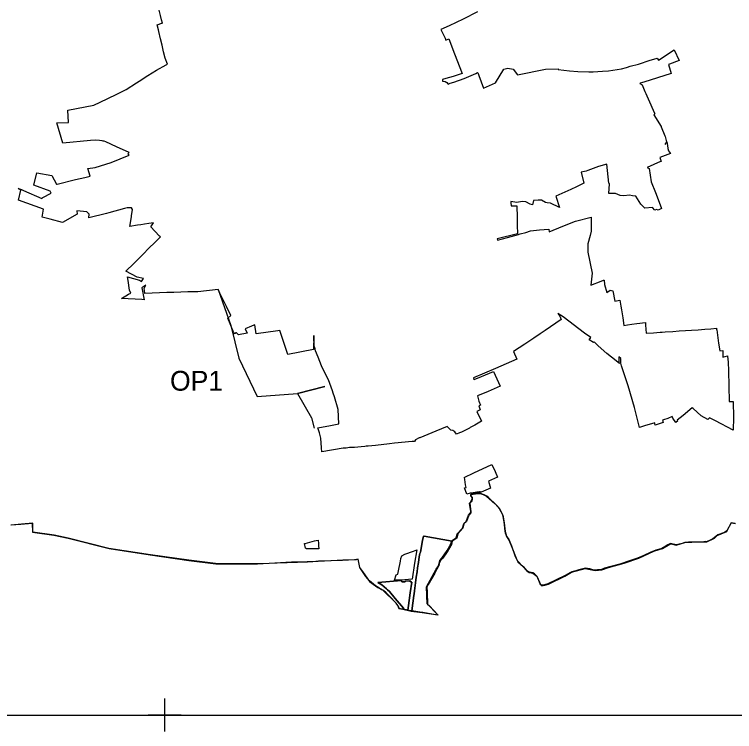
# Model space of a CAD drawing. Extents: x -478490 to -472450, y -1118050 to -1109550.
# Drawn here: x -477155 to -474975, y -1118050 to -1115880 of the extents above; entities that cross this region are included whole.
import ezdxf

# ---------------------------------------------------------------- set-up
doc = ezdxf.new("R2010")
doc.units = 0
for name, color, linetype in [('hranice kú', 7, 'Continuous'), ('Implicitní', 7, 'Continuous'), ('ObPÚ', 7, 'Continuous')]:
    doc.layers.add(name, color=color, linetype=linetype)

msp = doc.modelspace()

# ---------------------------------------------------------------- linework, layer by layer
at = {"layer": 'hranice kú'}
for p, q in [((-475773.3, -1117332.4), (-475752, -1117329.2)), ((-475772.9, -1117337.3), (-475773.3, -1117332.4)), ((-475773.1, -1117354.3), (-475768.7, -1117344)), ((-475770, -1117340.3), (-475772.9, -1117337.3)), ((-475768.7, -1117344), (-475770, -1117340.3)), ((-475752, -1117329.2), (-475745.4, -1117329.5)), ((-475745.4, -1117329.5), (-475736, -1117333)), ((-475736, -1117333), (-475725.4, -1117338.1)), ((-475725.4, -1117338.1), (-475700.6, -1117360.1)), ((-475777.5, -1117358.9), (-475773.1, -1117354.3)), ((-475773.7, -1117384.2), (-475777.5, -1117358.9)), ((-475700.6, -1117360.1), (-475690.7, -1117370.6)), ((-475780.7, -1117395.1), (-475774.1, -1117388)), ((-475774.1, -1117388), (-475773.7, -1117384.2)), ((-475690.7, -1117370.6), (-475685.4, -1117378)), ((-475685.4, -1117378), (-475676.7, -1117395.1)), ((-475787.5, -1117414.7), (-475780.7, -1117395.1)), ((-475676.7, -1117395.1), (-475671.9, -1117417.9)), ((-477165.8, -1117424.6), (-477134.7, -1117422.1)), ((-477134.7, -1117422.1), (-477100.4, -1117419)), ((-477100.4, -1117419), (-477099.3, -1117446.8)), ((-475798.5, -1117434.6), (-475794.6, -1117421.1)), ((-475794.6, -1117421.1), (-475787.5, -1117414.7)), ((-475671.9, -1117417.9), (-475669.7, -1117444.5)), ((-474998.9, -1117444.1), (-474985.7, -1117418)), ((-474985.7, -1117418), (-474972, -1117420.4)), ((-477099.3, -1117446.8), (-477035.2, -1117455.8)), ((-475817.6, -1117464.1), (-475814.3, -1117451.4)), ((-475814.3, -1117451.4), (-475798.5, -1117434.6)), ((-475669.7, -1117444.5), (-475665.3, -1117458.5)), ((-475027.8, -1117457.1), (-474998.9, -1117444.1)), ((-477035.2, -1117455.8), (-476991.4, -1117464.9)), ((-476991.4, -1117464.9), (-476867.7, -1117495.9)), ((-475833, -1117480.7), (-475831.5, -1117473.2)), ((-475831.5, -1117473.2), (-475817.6, -1117464.1)), ((-475665.3, -1117458.5), (-475658.2, -1117469.2)), ((-475658.2, -1117469.2), (-475650.2, -1117488)), ((-475059, -1117476.2), (-475035.7, -1117464.8)), ((-475035.7, -1117464.8), (-475027.8, -1117457.1)), ((-476867.7, -1117495.9), (-476743.2, -1117515.4)), ((-475844.9, -1117501.8), (-475835.7, -1117486.1)), ((-475835.7, -1117486.1), (-475833, -1117480.7)), ((-475650.2, -1117488), (-475638.7, -1117519.8)), ((-475219.6, -1117504.2), (-475193.7, -1117496.3)), ((-475193.7, -1117496.3), (-475171.4, -1117482.5)), ((-475171.4, -1117482.5), (-475166.6, -1117481.7)), ((-475166.6, -1117481.7), (-475151.7, -1117486)), ((-475151.7, -1117486), (-475125.2, -1117477.7)), ((-475125.2, -1117477.7), (-475104.3, -1117477.2)), ((-475104.3, -1117477.2), (-475059, -1117476.2)), ((-476743.2, -1117515.4), (-476626.6, -1117532.5)), ((-475860.6, -1117525.1), (-475844.9, -1117501.8)), ((-475264.7, -1117524.8), (-475219.6, -1117504.2)), ((-476626.6, -1117532.5), (-476544.9, -1117542)), ((-476419.1, -1117542), (-476383.4, -1117540.4)), ((-476383.4, -1117540.4), (-476335, -1117538.6)), ((-476161.9, -1117531.2), (-476125.1, -1117529.7)), ((-476125.1, -1117529.7), (-476118.9, -1117528.8)), ((-476118.9, -1117528.8), (-476114.9, -1117528.2)), ((-476114.9, -1117528.2), (-476109.7, -1117553.1)), ((-475871.5, -1117548.3), (-475867, -1117532.2)), ((-475867, -1117532.2), (-475860.6, -1117525.1)), ((-475638.7, -1117519.8), (-475631.3, -1117536.1)), ((-475631.3, -1117536.1), (-475615.2, -1117550.7)), ((-475357.1, -1117553.3), (-475309.3, -1117540.8)), ((-475309.3, -1117540.8), (-475264.7, -1117524.8)), ((-476544.9, -1117542), (-476419.1, -1117542)), ((-476109.7, -1117553.1), (-476101, -1117565.5)), ((-475884.7, -1117569.8), (-475878.1, -1117558.5)), ((-475878.1, -1117558.5), (-475871.5, -1117548.3)), ((-475615.2, -1117550.7), (-475604.2, -1117563.4)), ((-475468.7, -1117568), (-475426.9, -1117556.4)), ((-475426.9, -1117556.4), (-475397.4, -1117562.5)), ((-475397.4, -1117562.5), (-475376.6, -1117560.5)), ((-475376.6, -1117560.5), (-475357.1, -1117553.3)), ((-476101, -1117565.5), (-476080.1, -1117595.4)), ((-475907.7, -1117611.9), (-475884.7, -1117569.8)), ((-475604.2, -1117563.4), (-475596.5, -1117568.1)), ((-475596.5, -1117568.1), (-475585.2, -1117571.1)), ((-475585.2, -1117571.1), (-475573.8, -1117579.5)), ((-475573.8, -1117579.5), (-475565.7, -1117598.2)), ((-475538.1, -1117603.7), (-475489.2, -1117579.7)), ((-475489.2, -1117579.7), (-475468.7, -1117568)), ((-476080.1, -1117595.4), (-476057.9, -1117611.9)), ((-475565.7, -1117598.2), (-475562.9, -1117604.6)), ((-475562.9, -1117604.6), (-475558.3, -1117608.5)), ((-475549.6, -1117607.3), (-475538.1, -1117603.7)), ((-476057.9, -1117611.9), (-476054.4, -1117613.8)), ((-476054.4, -1117613.8), (-476051.1, -1117615.7)), ((-476051.1, -1117615.7), (-476048.5, -1117617)), ((-476048.5, -1117617), (-476046.4, -1117618.3)), ((-476046.4, -1117618.3), (-476043.5, -1117619.9)), ((-476043.5, -1117619.9), (-476040.8, -1117621.3)), ((-476040.8, -1117621.3), (-476035.4, -1117626.1)), ((-476035.4, -1117626.1), (-476004.1, -1117656)), ((-475905.2, -1117663.1), (-475907.7, -1117611.9)), ((-475558.3, -1117608.5), (-475549.6, -1117607.3)), ((-476004.1, -1117656), (-475996, -1117665.9)), ((-475996, -1117665.9), (-475991.2, -1117677.6)), ((-475872.8, -1117696.5), (-475905.2, -1117663.1)), ((-475991.2, -1117677.6), (-475978.7, -1117679.6)), ((-475978.7, -1117679.6), (-475953.9, -1117685.4)), ((-475953.9, -1117685.4), (-475920.8, -1117690)), ((-475920.8, -1117690), (-475872.8, -1117696.5))]:
    msp.add_line(p, q, dxfattribs=at)
msp.add_lwpolyline([(-476335, -1117538.6), (-476331.3, -1117538.5), (-476328.9, -1117538.5), (-476309.5, -1117537.6), (-476304, -1117537.5), (-476297.9, -1117537.3), (-476282.7, -1117536.7), (-476267.7, -1117535.9), (-476235.2, -1117534.5), (-476196.6, -1117532.7), (-476161.9, -1117531.2)], dxfattribs=at)
at = {"layer": 'Implicitní'}
for p, q in [((-476700.1, -1117950.1), (-476700.1, -1118050.1)), ((-476650.1, -1118000.1), (-476750.1, -1118000.1))]:
    msp.add_line(p, q, dxfattribs=at)
msp.add_lwpolyline([(-478440.1, -1118000.1), (-472500.1, -1118000.1), (-472500.1, -1109600.1), (-478440.1, -1109600.1)], close=True, dxfattribs=at)
msp.add_lwpolyline([(-476537.9, -1116712.5), (-476499.6, -1116820.8), (-476475.1, -1116919.5), (-476420.2, -1117035.8), (-476297.4, -1117027.1), (-476215, -1117005.8), (-476297.4, -1117027.1), (-476255.6, -1117100.3), (-476255.6, -1117100.3), (-476247.5, -1117131.7)], dxfattribs=at)
at = {"layer": 'ObPÚ'}
for p, q in [((-475744.6, -1117324.7), (-475747, -1117324)), ((-475742.5, -1117325.3), (-475744.6, -1117324.7))]:
    msp.add_line(p, q, dxfattribs=at)
for points in [[(-476716.8, -1116549.4), (-476742.1, -1116522.2), (-476733.5, -1116510), (-476747.3, -1116512.3), (-476761, -1116514.4), (-476772.2, -1116516.4), (-476782.1, -1116517.8), (-476805.1, -1116521.1), (-476800.4, -1116492.3), (-476799.8, -1116488.9), (-476796.8, -1116469.7), (-476799.8, -1116465.1), (-476813.2, -1116464.9), (-476821.5, -1116467.2), (-476869, -1116480.1), (-476875.9, -1116482), (-476929.6, -1116495.7), (-476928.6, -1116484.7), (-476935.1, -1116477.1), (-476965.2, -1116473.8), (-476964.1, -1116483.8), (-477009.1, -1116509.9), (-477046.3, -1116499.5), (-477070.7, -1116493.1), (-477066, -1116469.4), (-477142.6, -1116441.9), (-477135.3, -1116411.7), (-477143.2, -1116406.4), (-477133.2, -1116409.5), (-477127, -1116412.2), (-477072, -1116436.3), (-477068.2, -1116434.2), (-477043, -1116420.5), (-477046.2, -1116414.4), (-477096.2, -1116396.9), (-477087, -1116359.4), (-477041.6, -1116367.7), (-477027.1, -1116393.6), (-477024.7, -1116393), (-476969.7, -1116379.8), (-476941.5, -1116373.1), (-476924.9, -1116369.2), (-476932, -1116346), (-476910.3, -1116342.8), (-476862, -1116327.9), (-476806.8, -1116306.1), (-476811.6, -1116302), (-476807.6, -1116298), (-476845.7, -1116280.1), (-476878, -1116265), (-476883.2, -1116263.6), (-476885.7, -1116263.1), (-476889.1, -1116262.6), (-476896.8, -1116261.7), (-476908.9, -1116260.2), (-476924.1, -1116261.6), (-477007.9, -1116269), (-477025.9, -1116207.4), (-476990.5, -1116207), (-476992.4, -1116169.7), (-476913.9, -1116154.4), (-476895, -1116145), (-476846.1, -1116121.6), (-476816.5, -1116106.9), (-476785, -1116086.7), (-476776.6, -1116081.3), (-476750.7, -1116064.8), (-476724.3, -1116048.2), (-476695, -1116031.9), (-476691.4, -1116029.9), (-476697.9, -1116011.9), (-476703.4, -1115992.7), (-476707.7, -1115973.2), (-476712.7, -1115953.4), (-476717.9, -1115931.2), (-476718.9, -1115926.7), (-476722.5, -1115911.7), (-476708, -1115906.3), (-476706.6, -1115905.8), (-476709.3, -1115896.3), (-476712.4, -1115883.4), (-476716.3, -1115867)], [(-475753.2, -1115871.8), (-475796.4, -1115894.5), (-475838.6, -1115914.6), (-475863.6, -1115925.3), (-475850.8, -1115952.1), (-475848.8, -1115957.6), (-475839.8, -1115954), (-475822.7, -1115998.9), (-475799.8, -1116058.4), (-475826.7, -1116067.4), (-475849.1, -1116073.9), (-475859, -1116076.8), (-475858.5, -1116081.8), (-475850.5, -1116082.4), (-475846, -1116085.5), (-475841.5, -1116090.5), (-475835.8, -1116087.6), (-475824.7, -1116084.4), (-475793.6, -1116073.2), (-475757.8, -1116058.6), (-475752.6, -1116055.2), (-475751.9, -1116056.2), (-475751.3, -1116058.9), (-475749.1, -1116064.3), (-475735.2, -1116103), (-475699, -1116087), (-475673.7, -1116045.3), (-475661.5, -1116042.2), (-475645.4, -1116045.7), (-475632.5, -1116062.8), (-475547.6, -1116045), (-475509.3, -1116044.8), (-475509.4, -1116046.9), (-475475.1, -1116050.7), (-475449.8, -1116052.2), (-475416.4, -1116053.9), (-475403.4, -1116053.3), (-475374.7, -1116051.3), (-475356.5, -1116050.4), (-475317.7, -1116043.9), (-475302.2, -1116039.9), (-475298.9, -1116039.2), (-475291.5, -1116036.7), (-475266.1, -1116030), (-475230.2, -1116017.8), (-475212.6, -1116013.1), (-475209, -1116012.4), (-475205, -1116017.9), (-475157.9, -1115986.7), (-475143.1, -1116018.7), (-475171.7, -1116030.3), (-475175.1, -1116031.6), (-475166.6, -1116058.8), (-475250, -1116085.1), (-475260.4, -1116087.5), (-475261.4, -1116089.2), (-475254.8, -1116092.9), (-475246.3, -1116113), (-475243.5, -1116119.3), (-475240.6, -1116126), (-475236.6, -1116135), (-475217.4, -1116178.1), (-475216.4, -1116180.6), (-475219.2, -1116183.5), (-475197.7, -1116219.3), (-475197.5, -1116220.1), (-475186.2, -1116246.7), (-475185.4, -1116248.9), (-475181.2, -1116265.4), (-475185.4, -1116273.3), (-475179.8, -1116265.2), (-475178.2, -1116276.8), (-475177.1, -1116285), (-475175.1, -1116292.7)], [(-475175.1, -1116292.7), (-475169.4, -1116300.7), (-475201.2, -1116312.9), (-475197.7, -1116324.4), (-475199.7, -1116325.2), (-475239.7, -1116342.5), (-475233.8, -1116345.8), (-475227.7, -1116385.9), (-475214.4, -1116418.3), (-475197.3, -1116464.1), (-475196.2, -1116466.6), (-475206.7, -1116472.6), (-475211.8, -1116470.3), (-475216.6, -1116472.3), (-475223.2, -1116464.3), (-475246.3, -1116465.9), (-475258.3, -1116454.1), (-475273.6, -1116430.2), (-475283.6, -1116428.6), (-475293.4, -1116427.1), (-475310, -1116428.3), (-475321.7, -1116428), (-475335.4, -1116421.9), (-475355.5, -1116421.9), (-475353.9, -1116392.4), (-475355.8, -1116390.7), (-475361.4, -1116332.7), (-475386.9, -1116339.9), (-475419.2, -1116352.4), (-475423.8, -1116353.6), (-475439, -1116357.5), (-475430.9, -1116390.6), (-475453.5, -1116401.6), (-475470.5, -1116409.5), (-475516.3, -1116429.6), (-475504.9, -1116463.8), (-475531.9, -1116451.3), (-475542.4, -1116449.8), (-475547.1, -1116448.7), (-475559.9, -1116441.8), (-475569.8, -1116442.1), (-475583.6, -1116442.6), (-475586.4, -1116455.5), (-475593.7, -1116453.8), (-475606.8, -1116446.9), (-475618.2, -1116446.2), (-475633.8, -1116448.7), (-475652, -1116445.7), (-475652.2, -1116449.6), (-475650.9, -1116458.7), (-475634, -1116458.7), (-475633.3, -1116494.1), (-475633, -1116516.4), (-475632.9, -1116517.5), (-475631.8, -1116543.6), (-475693.2, -1116558.8), (-475692.2, -1116562.7), (-475661.8, -1116554.6), (-475628.7, -1116545.5), (-475623.9, -1116544.2), (-475607, -1116540), (-475592.9, -1116535.1), (-475565.4, -1116531.9), (-475537.3, -1116529.1), (-475536.7, -1116537.2), (-475494.7, -1116520.7), (-475456.5, -1116505.8), (-475409.4, -1116493.6), (-475409.3, -1116535.9), (-475412.3, -1116549), (-475419.4, -1116573.5), (-475419, -1116599.7), (-475406.5, -1116662.9), (-475410.2, -1116698.6), (-475379.2, -1116686.8), (-475372.2, -1116684.3), (-475370, -1116683.5), (-475368.5, -1116696.7), (-475361.8, -1116721.1), (-475351.9, -1116714.1), (-475343.5, -1116716.4), (-475337.6, -1116747.5), (-475322.6, -1116744.6), (-475319.8, -1116762.9), (-475317.8, -1116774.1), (-475313.4, -1116797.9), (-475310.2, -1116821.1), (-475299.6, -1116819.4), (-475286, -1116817.2), (-475271, -1116814.7), (-475244.9, -1116812.1), (-475244.2, -1116820), (-475242.4, -1116844.2), (-475220.3, -1116843.3), (-475200.7, -1116841.8), (-475194.4, -1116841.2)], [(-475821.3, -1117143.2), (-475827.5, -1117139.1), (-475834.2, -1117137.6), (-475844.4, -1117127.1), (-475878.8, -1117141), (-475928, -1117160.8), (-475929.8, -1117161.5), (-475941.2, -1117167.3), (-475944, -1117172.5), (-475951.3, -1117172.4), (-476004.5, -1117177.3), (-476018.9, -1117179.2), (-476061.7, -1117184), (-476084.3, -1117186.2), (-476089.5, -1117186.6), (-476094, -1117187), (-476104.8, -1117188), (-476125.8, -1117190), (-476140.4, -1117190.8), (-476151, -1117191.9), (-476159.5, -1117192.8), (-476224.1, -1117203.1), (-476225.4, -1117191.1), (-476226.7, -1117162.3), (-476231.3, -1117146.2), (-476236.3, -1117130.9), (-476197.9, -1117123.9), (-476173.1, -1117118.5), (-476175.1, -1117075.5), (-476185.9, -1117036.7), (-476189.6, -1117026.3), (-476192, -1117018.9), (-476203.9, -1116985.9), (-476220.3, -1116954.1), (-476224.8, -1116942.7), (-476235.1, -1116917.1), (-476243.4, -1116897.3), (-476244.9, -1116886.6), (-476247.7, -1116887.1), (-476248.8, -1116851.6), (-476249, -1116893.6), (-476326.6, -1116908.5), (-476339.7, -1116869.9), (-476351, -1116836.6), (-476357.4, -1116837.7), (-476422.9, -1116845.9), (-476427.4, -1116819.4), (-476430.3, -1116820.4), (-476436.9, -1116823.5), (-476455.7, -1116831.7), (-476450.1, -1116844), (-476476, -1116849.4), (-476482.1, -1116843.1), (-476483.7, -1116843.8), (-476488.8, -1116845.9), (-476490.1, -1116842.9), (-476509, -1116798.8), (-476499.6, -1116790.5), (-476512.7, -1116763.7), (-476522.7, -1116743.4), (-476532.6, -1116723.3), (-476537.9, -1116712.5), (-476599.3, -1116718.8), (-476629.5, -1116719.4), (-476650.7, -1116720.2), (-476671.7, -1116720.8), (-476692.9, -1116721.6), (-476759.4, -1116724), (-476760.7, -1116714.9), (-476761.7, -1116709.6), (-476757.2, -1116699.1), (-476768.7, -1116707.4), (-476762, -1116743), (-476768.7, -1116742.8), (-476830.9, -1116739.2), (-476809.4, -1116726.4), (-476801.8, -1116722.8), (-476806.4, -1116714.5), (-476810.3, -1116684.8), (-476811.8, -1116673.6), (-476775.7, -1116683.8), (-476770.1, -1116687.8), (-476764, -1116678.9), (-476783.5, -1116674.4), (-476817.6, -1116656.8), (-476793.5, -1116634), (-476780, -1116620.5), (-476777, -1116617.7), (-476761.2, -1116601.3), (-476751.7, -1116591.3), (-476745.1, -1116584.2), (-476732.8, -1116572.5), (-476722.4, -1116563.2), (-476712.3, -1116553.3), (-476715.3, -1116551), (-476716.8, -1116549.4)], [(-475194.4, -1116841.2), (-475185.4, -1116840.5), (-475161.7, -1116839.1), (-475142.9, -1116837.6), (-475124, -1116836.4), (-475105, -1116835), (-475085.7, -1116834.1), (-475065.1, -1116832.4), (-475047.4, -1116830.9), (-475030, -1116829.5), (-475029.4, -1116833.9), (-475028.6, -1116833.9), (-475023.8, -1116874.9), (-475019.8, -1116897.4), (-475011, -1116896.8), (-475010.4, -1116909.6), (-475010.4, -1116916.5), (-474996.6, -1116913), (-474996.4, -1116914.1), (-474994.6, -1116931.6), (-474993.4, -1116958.1), (-474991.2, -1117050.8), (-474978.9, -1117051.1), (-474978.1, -1117099.4), (-474979.1, -1117137.4), (-475032.7, -1117109.2), (-475050.7, -1117100.4), (-475056.1, -1117105.6), (-475076, -1117094.2), (-475100.9, -1117072.7), (-475103.2, -1117070.5), (-475130.9, -1117093.6), (-475148.6, -1117107.7), (-475146.9, -1117109.8), (-475153.2, -1117114.5), (-475161.6, -1117101.4), (-475164.2, -1117097), (-475176.8, -1117102.4), (-475190.4, -1117106.6), (-475193, -1117107.4), (-475191.2, -1117114.5), (-475215, -1117122.7), (-475216.2, -1117118.1), (-475216.8, -1117115.6), (-475247.6, -1117125.1), (-475262.7, -1117129.7), (-475267.7, -1117109.4), (-475278.3, -1117069.6), (-475297.5, -1117003.4), (-475317.6, -1116942.9), (-475319.3, -1116935), (-475319.6, -1116920.8), (-475325.4, -1116915.5), (-475324.9, -1116932.2), (-475323.6, -1116936.3), (-475347.7, -1116917), (-475362, -1116905.8), (-475387.6, -1116882.8), (-475400.2, -1116870.4), (-475402.3, -1116872.8), (-475415.1, -1116864), (-475409.9, -1116857), (-475429, -1116844), (-475493.6, -1116794.9), (-475510, -1116785), (-475504.4, -1116792.7), (-475500.2, -1116802.9), (-475548.7, -1116836.1), (-475563.2, -1116845.9), (-475582.4, -1116859), (-475609.9, -1116877.6), (-475644, -1116900.2), (-475634.1, -1116923.5), (-475698.2, -1116950.9), (-475765.5, -1116979.2), (-475764.2, -1116985.3), (-475762.8, -1116984.7), (-475740.8, -1116975.6), (-475704.4, -1116959.9), (-475684.8, -1117005), (-475721.1, -1117020.7), (-475752.9, -1117034.2), (-475749.2, -1117050), (-475744.5, -1117062.5), (-475748.9, -1117064.2), (-475744.9, -1117076.6), (-475754.6, -1117081.6), (-475740.7, -1117110.4), (-475761.5, -1117122.4), (-475769.3, -1117126.9), (-475775.6, -1117130.1), (-475776.9, -1117131.4), (-475801.9, -1117143.8), (-475807.1, -1117146.1), (-475816.2, -1117150.3), (-475821.3, -1117143.2)], [(-475710, -1117241.8), (-475709.1, -1117243.6), (-475700.1, -1117263.1), (-475692.4, -1117280.1), (-475720.3, -1117292.4), (-475713.9, -1117313), (-475742.3, -1117325.9), (-475744.3, -1117325.4), (-475747.1, -1117325.2), (-475755.1, -1117325.3), (-475766.7, -1117327.6), (-475774.9, -1117328.9), (-475785.3, -1117331.9), (-475792, -1117312.6), (-475790.1, -1117312), (-475787.6, -1117311.1), (-475788.9, -1117303), (-475791.1, -1117287.2), (-475791.6, -1117285.8), (-475792.8, -1117282.4), (-475793.3, -1117280.9), (-475763.7, -1117266.8), (-475710, -1117241.8)], [(-475198.5, -1117496.9), (-475213.9, -1117501.5), (-475228.9, -1117507.4), (-475249.6, -1117517.1), (-475268.9, -1117525.3), (-475289.9, -1117532.2), (-475322.2, -1117543.7), (-475349.4, -1117550.5), (-475368.4, -1117555.9), (-475377.8, -1117559.3), (-475383.5, -1117560.7), (-475389.5, -1117560.4), (-475400.9, -1117561.8), (-475413.6, -1117557.9), (-475426.3, -1117555.6), (-475446.3, -1117560.1), (-475455.6, -1117563.4), (-475467.2, -1117566.3), (-475474.1, -1117569.3), (-475488, -1117577.9), (-475515.5, -1117590.5), (-475540.5, -1117602.8), (-475554.8, -1117606.9), (-475558.9, -1117606.6), (-475561.4, -1117605.6), (-475563.8, -1117603.3), (-475572.2, -1117580.4), (-475580.7, -1117572.9), (-475585.9, -1117569.9), (-475595.6, -1117567.1), (-475604.5, -1117562.3), (-475615.8, -1117550), (-475631.3, -1117534.8), (-475635.3, -1117526.5), (-475648.5, -1117493.4), (-475653.1, -1117480.5), (-475657.3, -1117471.2), (-475665.2, -1117457.3), (-475668.2, -1117449.8), (-475669.4, -1117443.4), (-475672.3, -1117415.6), (-475676.7, -1117394.5), (-475681.4, -1117384.9), (-475687.6, -1117373.9), (-475695.2, -1117364.7), (-475720.1, -1117341.3), (-475725.2, -1117337.8), (-475733.2, -1117333.4), (-475747.2, -1117328.6), (-475754.8, -1117328.7), (-475760.6, -1117329.4), (-475770.6, -1117331.7), (-475773.2, -1117331.8), (-475773.5, -1117335), (-475772.5, -1117337.4), (-475769.1, -1117340.7), (-475769.1, -1117342.3), (-475769.2, -1117346.8), (-475770, -1117352.1), (-475772.1, -1117354.5), (-475776.3, -1117358.9), (-475773, -1117385.1), (-475773.4, -1117388.3), (-475779.3, -1117394.7), (-475783.8, -1117405.7), (-475786.5, -1117414.6), (-475794, -1117421.4), (-475797.1, -1117434.2), (-475812.5, -1117451.2), (-475815.7, -1117464.3), (-475829.4, -1117473.5), (-475914.9, -1117458.4), (-475916.9, -1117458.2), (-475919.5, -1117472.1), (-475925.9, -1117507.1), (-475927.6, -1117510.8), (-475929.4, -1117521.1), (-475931.8, -1117538.7), (-475934.6, -1117554.7), (-475936.1, -1117566.1), (-475938.2, -1117582.8), (-475940.3, -1117599.7), (-475943.8, -1117623.9), (-475945, -1117632.9), (-475945.9, -1117637.9), (-475951.7, -1117685.1), (-475955.2, -1117684.4), (-475964.2, -1117682.6), (-475962, -1117668.4), (-475956.7, -1117630.6), (-475952.3, -1117598), (-475954.6, -1117598.1), (-475955, -1117594.8), (-475956.8, -1117595), (-475958.7, -1117595.2), (-475958.8, -1117593.6)], [(-475958.8, -1117593.6), (-475972.4, -1117594.8), (-475972.3, -1117596.4), (-475982.5, -1117597.2), (-475982.8, -1117592.9), (-476055, -1117598.4), (-476042.1, -1117606.1), (-476028.8, -1117617.9), (-476025.5, -1117620.8), (-476019.5, -1117625.8), (-476002, -1117647), (-475977.1, -1117676.9), (-475976.7, -1117680), (-475983.3, -1117679.3), (-475989, -1117677.7), (-475994, -1117668.3), (-475999.4, -1117660.9), (-476018.3, -1117641), (-476029.3, -1117630.2), (-476038, -1117622.8), (-476044.7, -1117618.6), (-476051.6, -1117615.3), (-476061.6, -1117608.9), (-476079.9, -1117594.1), (-476091, -1117580.9), (-476108.8, -1117553.8), (-476114, -1117528.4), (-476124.3, -1117530.1), (-476161, -1117531.2), (-476195.9, -1117533.1), (-476234.3, -1117534.6), (-476239.3, -1117534.9), (-476242.1, -1117535), (-476268.1, -1117536.1), (-476315.8, -1117537.8), (-476383.3, -1117541), (-476418.4, -1117542.7), (-476545.7, -1117541.3), (-476626.5, -1117531.7), (-476742.5, -1117514.7), (-476868.4, -1117495.6), (-476991.4, -1117464.8), (-477034.1, -1117456), (-477098.3, -1117446.9), (-477099.1, -1117418.9), (-477133.3, -1117422.8), (-477164, -1117425.1)], [(-474973.5, -1117420.4), (-474985.4, -1117417.8), (-474998.6, -1117442.1), (-475005.2, -1117447.5), (-475026, -1117454.6), (-475041.2, -1117466.8), (-475046.5, -1117469.7), (-475059.7, -1117475.4), (-475063.6, -1117475.2), (-475074, -1117476.3), (-475114.8, -1117476.6), (-475125.6, -1117477.5), (-475134.1, -1117480.6), (-475152.1, -1117484.6), (-475168.9, -1117481), (-475176.6, -1117484.4), (-475182.5, -1117488.4), (-475198.5, -1117496.9)], [(-476235, -1117470.3), (-476234.9, -1117472.9), (-476234.7, -1117478.9), (-476234.1, -1117489.1), (-476233, -1117496.2), (-476232.8, -1117497.4), (-476246.2, -1117496.9), (-476271, -1117497.1), (-476274, -1117494.7), (-476276.7, -1117480.9), (-476275, -1117480.4), (-476246.5, -1117473.2), (-476241.6, -1117471.9), (-476235, -1117470.3)], [(-475919.5, -1117472.1), (-475916.9, -1117458.2), (-475914.9, -1117458.4), (-475829.4, -1117473.5), (-475831.9, -1117483.6), (-475833.9, -1117486.9), (-475844.8, -1117506.3), (-475858.4, -1117525.5), (-475865.5, -1117532.6), (-475866.6, -1117537), (-475868.6, -1117541.6), (-475870.1, -1117548.5), (-475871.2, -1117549.7), (-475876.2, -1117558.8), (-475882.6, -1117570.2), (-475902.5, -1117604.8), (-475906.8, -1117612.2), (-475905.7, -1117629.1), (-475903.9, -1117664.4), (-475898.5, -1117669.1), (-475871.7, -1117697.5), (-475884.8, -1117695.4), (-475919, -1117689.8), (-475927.3, -1117688.7), (-475951.7, -1117685.1), (-475945.9, -1117637.9), (-475945, -1117632.9), (-475943.8, -1117623.9), (-475940.3, -1117599.7), (-475938.2, -1117582.8), (-475936.1, -1117566.1), (-475934.6, -1117554.7), (-475931.8, -1117538.7), (-475929.4, -1117521.1), (-475927.6, -1117510.8), (-475925.9, -1117507.1), (-475919.5, -1117472.1)], [(-475937.1, -1117500.3), (-475943.5, -1117540.5), (-475950.6, -1117589.2), (-475972.8, -1117590.3), (-476004.6, -1117592.3), (-475999.6, -1117575.3), (-475994.2, -1117573.4), (-475992.2, -1117563.2), (-475986.2, -1117534.1), (-475984.9, -1117525.8), (-475982, -1117518.2), (-475972.8, -1117513.2), (-475947.2, -1117503.8), (-475937.1, -1117500.3)], [(-476055, -1117598.4), (-475982.8, -1117592.9), (-475982.5, -1117597.2), (-475972.3, -1117596.4), (-475972.4, -1117594.8), (-475958.8, -1117593.6), (-475958.7, -1117595.2), (-475956.8, -1117595), (-475955, -1117594.8), (-475954.6, -1117598.1), (-475952.3, -1117598), (-475956.7, -1117630.6), (-475962, -1117668.4), (-475964.2, -1117682.6), (-475976.7, -1117680), (-475977.1, -1117676.9), (-476002, -1117647), (-476019.5, -1117625.8), (-476025.5, -1117620.8), (-476028.8, -1117617.9), (-476042.1, -1117606.1), (-476055, -1117598.4)]]:
    msp.add_lwpolyline(points, dxfattribs=at)

# ---------------------------------------------------------------- texts
at = {"layer": 'Implicitní'}
msp.add_text('OP1', height=60, dxfattribs=at).set_placement((-476683.6, -1117018.4))

doc.saveas('drawing.dxf')
